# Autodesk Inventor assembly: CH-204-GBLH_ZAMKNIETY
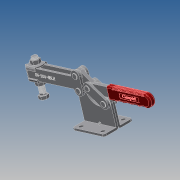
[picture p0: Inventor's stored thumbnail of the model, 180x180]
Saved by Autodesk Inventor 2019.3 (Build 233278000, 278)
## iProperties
Company: Î¢ÈíÖÐ¹ú
Created: 2012-09
Part Number: CH-204-GBLH_ZAMKNIETY
Material: Ogólny
Description: STEP AP203
Document SubType Name: Assembly
Designer: CADENGINEERING4
Sending System: SolidWorks 2010
Preprocessor: SwSTEP 2.0
Title: CH-204-GBLH.STEP
Author: Î¢ÈíÓÃ»§
Revision Number: ÈÎºÎ
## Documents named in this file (11)
- E:\STRONA\Horizontal toggle clamp\CH-204-GBLH\CH-204-GBLH_ZAMKNIETY.iam
- E:\STRONA\Horizontal toggle clamp\CH-204-GBLH\CH-FC-12300-01___.ipt
- E:\STRONA\Horizontal toggle clamp\CH-204-GBLH\204-GB-08___.ipt
- E:\STRONA\Horizontal toggle clamp\CH-204-GBLH\204-GB-05___.ipt
- E:\STRONA\Horizontal toggle clamp\CH-204-GBLH\204-GBLH-01___.ipt
- E:\STRONA\Horizontal toggle clamp\CH-204-GBLH\204-GB-06___.ipt
- E:\STRONA\Horizontal toggle clamp\CH-204-GBLH\204-GB-04___.ipt
- E:\STRONA\Horizontal toggle clamp\CH-204-GBLH\204-G-03___.iam
- E:\STRONA\Horizontal toggle clamp\CH-204-GBLH\FW120(2)___.ipt
- E:\STRONA\Horizontal toggle clamp\CH-204-GBLH\204-GBLH-02___.ipt
- E:\STRONA\Horizontal toggle clamp\CH-204-GBLH\CH-FC-12130___.ipt
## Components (22 placed, 22 different names)
1. CH-FC-12300-01____1 — Zestawiające:3, Zestawiające:6
2. 204-GB-08____2 — Zestawiające:23, Zestawiające:26
3. 204-GB-05____3 — Zestawiające:11, Zestawiające:12, Zestawiające:14
4. 204-GBLH-01____4 — Zestawiające:10, Zestawiające:11, Zestawiające:12, Zestawiające:13, Zestawiające:16, Zestawiające:17, Zestawiające:29, Zestawiające:30, Zestawiające:31, Zestawiające:32, Zestawiające:33, Przejściowe:1
5. 204-GB-06____5 — Zestawiające:38, Zestawiające:40
6. 204-GB-04____6 — Zestawiające:15, Zestawiające:16, Zestawiające:18, Zestawiające:19, Zestawiające:21
7. 204-G-03____7 [sub-assembly] — Zestawiające:27, Zestawiające:28, Zestawiające:43, Przejściowe:1
8. 204-GB-05____8 — Zestawiające:29, Zestawiające:32
9. FW120(2)____9 — Równoległe:1, Równoległe:2, Zestawiające:1, Zestawiające:7, Zestawiające:8
10. 204-GBLH-02____10 — Równoległe:1, Zestawiające:5, Zestawiające:8, Zestawiające:9, Zestawiające:34, Zestawiające:35, Zestawiające:36, Zestawiające:37, Zestawiające:38, Zestawiające:39, Zestawiające:40, Zestawiające:41, Zestawiające:42
11. 204-GB-08____11 — Zestawiające:24, Zestawiające:25, Zestawiające:28
12. 204-GB-06____12 — Zestawiające:19, Zestawiające:21
13. 204-GB-06____13 — Zestawiające:37, Zestawiające:39
14. 204-GB-08____14 — Zestawiające:41, Zestawiające:42, Zestawiające:43
15. 204-GB-08____15 — Zestawiające:33, Zestawiające:35, Zestawiające:36
16. 204-GB-06____16 — Zestawiające:20, Zestawiające:22, Zestawiające:27
17. 204-GB-05____17 — Zestawiające:10, Zestawiające:13, Zestawiające:15
18. CH-FC-12130____18 — Równoległe:3, Zestawiające:1, Zestawiające:2, Zestawiające:3, Zestawiające:4, Zestawiające:9
19. CH-FC-12300-01____19 — Równoległe:3, Zestawiające:2, Zestawiające:7
20. FW120(2)____20 — Równoległe:2, Zestawiające:4, Zestawiające:5, Zestawiające:6
21. 204-GB-05____21 — Zestawiające:30, Zestawiające:31, Zestawiające:34
22. 204-GB-04____22 — Zestawiające:14, Zestawiające:17, Zestawiające:18, Zestawiające:20, Zestawiające:22, Zestawiające:23, Zestawiające:24, Zestawiające:25, Zestawiające:26
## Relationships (47: Mate 43, Flush 3, Transitional 1)
- Równoległe:1 [Flush]: FW120(2)____9 ↔ 204-GBLH-02____10
- Równoległe:2 [Flush]: FW120(2)____9 ↔ FW120(2)____20
- Równoległe:3 [Flush]: CH-FC-12130____18 ↔ CH-FC-12300-01____19
- Zestawiające:1 [Mate]: FW120(2)____9 ↔ CH-FC-12130____18
- Zestawiające:2 [Mate]: CH-FC-12130____18 ↔ CH-FC-12300-01____19
- Zestawiające:3 [Mate]: CH-FC-12300-01____1 ↔ CH-FC-12130____18
- Zestawiające:4 [Mate]: CH-FC-12130____18 ↔ FW120(2)____20
- Zestawiające:5 [Mate]: 204-GBLH-02____10 ↔ FW120(2)____20
- Zestawiające:6 [Mate]: CH-FC-12300-01____1 ↔ FW120(2)____20
- Zestawiające:7 [Mate]: FW120(2)____9 ↔ CH-FC-12300-01____19
- Zestawiające:8 [Mate]: FW120(2)____9 ↔ 204-GBLH-02____10
- Zestawiające:9 [Mate]: 204-GBLH-02____10 ↔ CH-FC-12130____18
- Zestawiające:10 [Mate]: 204-GBLH-01____4 ↔ 204-GB-05____17
- Zestawiające:11 [Mate]: 204-GB-05____3 ↔ 204-GBLH-01____4
- Zestawiające:12 [Mate]: 204-GB-05____3 ↔ 204-GBLH-01____4
- Zestawiające:13 [Mate]: 204-GBLH-01____4 ↔ 204-GB-05____17
- Zestawiające:14 [Mate]: 204-GB-05____3 ↔ 204-GB-04____22
- Zestawiające:15 [Mate]: 204-GB-04____6 ↔ 204-GB-05____17
- Zestawiające:16 [Mate]: 204-GBLH-01____4 ↔ 204-GB-04____6
- Zestawiające:17 [Mate]: 204-GBLH-01____4 ↔ 204-GB-04____22
- Zestawiające:18 [Mate]: 204-GB-04____6 ↔ 204-GB-04____22
- Zestawiające:19 [Mate]: 204-GB-04____6 ↔ 204-GB-06____12
- Zestawiające:20 [Mate]: 204-GB-06____16 ↔ 204-GB-04____22
- Zestawiające:21 [Mate]: 204-GB-04____6 ↔ 204-GB-06____12
- Zestawiające:22 [Mate]: 204-GB-06____16 ↔ 204-GB-04____22
- Zestawiające:23 [Mate]: 204-GB-08____2 ↔ 204-GB-04____22
- Zestawiające:24 [Mate]: 204-GB-08____11 ↔ 204-GB-04____22
- Zestawiające:25 [Mate]: 204-GB-08____11 ↔ 204-GB-04____22
- Zestawiające:26 [Mate]: 204-GB-08____2 ↔ 204-GB-04____22
- Zestawiające:27 [Mate]: 204-G-03____7 ↔ 204-GB-06____16
- Zestawiające:28 [Mate]: 204-G-03____7 ↔ 204-GB-08____11
- Zestawiające:29 [Mate]: 204-GBLH-01____4 ↔ 204-GB-05____8
- Zestawiające:30 [Mate]: 204-GBLH-01____4 ↔ 204-GB-05____21
- Zestawiające:31 [Mate]: 204-GBLH-01____4 ↔ 204-GB-05____21
- Zestawiające:32 [Mate]: 204-GBLH-01____4 ↔ 204-GB-05____8
- Zestawiające:33 [Mate]: 204-GBLH-01____4 ↔ 204-GB-08____15
- Zestawiające:34 [Mate]: 204-GBLH-02____10 ↔ 204-GB-05____21
- Zestawiające:35 [Mate]: 204-GBLH-02____10 ↔ 204-GB-08____15
- Zestawiające:36 [Mate]: 204-GBLH-02____10 ↔ 204-GB-08____15
- Zestawiające:37 [Mate]: 204-GBLH-02____10 ↔ 204-GB-06____13
- Zestawiające:38 [Mate]: 204-GB-06____5 ↔ 204-GBLH-02____10
- Zestawiające:39 [Mate]: 204-GBLH-02____10 ↔ 204-GB-06____13
- Zestawiające:40 [Mate]: 204-GB-06____5 ↔ 204-GBLH-02____10
- Zestawiające:41 [Mate]: 204-GBLH-02____10 ↔ 204-GB-08____14
- Zestawiające:42 [Mate]: 204-GBLH-02____10 ↔ 204-GB-08____14
- Zestawiające:43 [Mate]: 204-G-03____7 ↔ 204-GB-08____14
- Przejściowe:1 [Transitional]: 204-GBLH-01____4 ↔ 204-G-03____7
